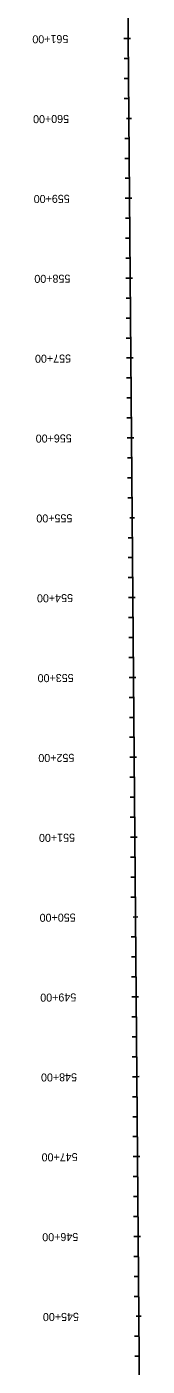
# Model space of a CAD drawing. Extents: x 23417911 to 23421158, y 6737892 to 6791804.
# Drawn here: x 23420755 to 23420891, y 6780008 to 6781685 of the extents above; entities that cross this region are included whole.
import ezdxf

# ---------------------------------------------------------------- set-up
doc = ezdxf.new("R2010")
doc.units = 0
for name, color, linetype in [('Alignment', 7, 'Continuous'), ('TextAlignmentLrg', 7, 'Continuous'), ('TextAlignmentSml', 7, 'Continuous')]:
    doc.layers.add(name, color=color, linetype=linetype)

msp = doc.modelspace()

# ---------------------------------------------------------------- linework, layer by layer
at = {"layer": 'Alignment'}
msp.add_line((23420888.7, 6779969.4), (23420840.8, 6785772.8), dxfattribs=at)
msp.add_line((23420888.7, 6779969.4), (23420840.8, 6785772.8), dxfattribs=at)
at = {"layer": 'TextAlignmentLrg'}
for p, q in [((23420874.7, 6781670.2), (23420869.2, 6781670.1)), ((23420872.4, 6781570.2), (23420878.6, 6781570.2)), ((23420876.3, 6781470.2), (23420870.9, 6781470.2)), ((23420877.2, 6781370.2), (23420871.7, 6781370.2)), ((23420878, 6781270.2), (23420872.5, 6781270.2)), ((23420878.8, 6781170.2), (23420873.3, 6781170.2)), ((23420876.6, 6781070.2), (23420882.7, 6781070.2)), ((23420880.5, 6780970.2), (23420875, 6780970.2)), ((23420881.3, 6780870.2), (23420875.8, 6780870.2)), ((23420882.1, 6780770.2), (23420876.6, 6780770.2)), ((23420882.9, 6780670.2), (23420877.5, 6780670.2)), ((23420880.7, 6780570.2), (23420886.8, 6780570.3)), ((23420884.6, 6780470.2), (23420879.1, 6780470.2)), ((23420885.4, 6780370.2), (23420879.9, 6780370.2)), ((23420886.2, 6780270.2), (23420880.8, 6780270.2)), ((23420887.1, 6780170.2), (23420881.6, 6780170.2)), ((23420884.8, 6780070.2), (23420890.9, 6780070.3))]:
    msp.add_line(p, q, dxfattribs=at)
at = {"layer": 'TextAlignmentSml'}
for p, q in [((23420871.6, 6781670.2), (23420877.7, 6781670.2)), ((23420874.9, 6781645.2), (23420869.4, 6781645.1)), ((23420875.1, 6781620.2), (23420869.6, 6781620.1)), ((23420875.3, 6781595.2), (23420869.8, 6781595.1)), ((23420872.4, 6781570.2), (23420878.6, 6781570.2)), ((23420875.7, 6781545.2), (23420870.3, 6781545.2)), ((23420875.9, 6781520.2), (23420870.5, 6781520.2)), ((23420876.1, 6781495.2), (23420870.7, 6781495.2)), ((23420873.3, 6781470.2), (23420879.4, 6781470.2)), ((23420876.5, 6781445.2), (23420871.1, 6781445.2)), ((23420876.7, 6781420.2), (23420871.3, 6781420.2)), ((23420876.9, 6781395.2), (23420871.5, 6781395.2)), ((23420874.1, 6781370.2), (23420880.2, 6781370.2)), ((23420877.4, 6781345.2), (23420871.9, 6781345.2)), ((23420877.6, 6781320.2), (23420872.1, 6781320.2)), ((23420877.8, 6781295.2), (23420872.3, 6781295.2)), ((23420874.9, 6781270.2), (23420881, 6781270.2)), ((23420878.2, 6781245.2), (23420872.7, 6781245.2)), ((23420878.4, 6781220.2), (23420872.9, 6781220.2)), ((23420878.6, 6781195.2), (23420873.1, 6781195.2)), ((23420875.7, 6781170.2), (23420881.9, 6781170.2)), ((23420879, 6781145.2), (23420873.6, 6781145.2)), ((23420879.2, 6781120.2), (23420873.8, 6781120.2)), ((23420879.4, 6781095.2), (23420874, 6781095.2)), ((23420876.6, 6781070.2), (23420882.7, 6781070.2)), ((23420879.8, 6781045.2), (23420874.4, 6781045.2)), ((23420880, 6781020.2), (23420874.6, 6781020.2)), ((23420880.2, 6780995.2), (23420874.8, 6780995.2)), ((23420877.4, 6780970.2), (23420883.5, 6780970.2)), ((23420880.7, 6780945.2), (23420875.2, 6780945.2)), ((23420880.9, 6780920.2), (23420875.4, 6780920.2)), ((23420881.1, 6780895.2), (23420875.6, 6780895.2)), ((23420878.2, 6780870.2), (23420884.3, 6780870.2)), ((23420881.5, 6780845.2), (23420876, 6780845.2)), ((23420881.7, 6780820.2), (23420876.2, 6780820.2)), ((23420881.9, 6780795.2), (23420876.4, 6780795.2)), ((23420879, 6780770.2), (23420885.2, 6780770.2)), ((23420882.3, 6780745.2), (23420876.9, 6780745.2)), ((23420882.5, 6780720.2), (23420877.1, 6780720.2)), ((23420882.7, 6780695.2), (23420877.3, 6780695.2)), ((23420879.9, 6780670.2), (23420886, 6780670.3)), ((23420883.1, 6780645.2), (23420877.7, 6780645.2)), ((23420883.3, 6780620.2), (23420877.9, 6780620.2)), ((23420883.5, 6780595.2), (23420878.1, 6780595.2)), ((23420880.7, 6780570.2), (23420886.8, 6780570.3)), ((23420884, 6780545.2), (23420878.5, 6780545.2)), ((23420884.2, 6780520.2), (23420878.7, 6780520.2)), ((23420884.4, 6780495.2), (23420878.9, 6780495.2)), ((23420881.5, 6780470.2), (23420887.6, 6780470.3)), ((23420884.8, 6780445.2), (23420879.3, 6780445.2)), ((23420885, 6780420.2), (23420879.5, 6780420.2)), ((23420885.2, 6780395.2), (23420879.7, 6780395.2)), ((23420882.3, 6780370.2), (23420888.5, 6780370.3)), ((23420885.6, 6780345.2), (23420880.2, 6780345.2)), ((23420885.8, 6780320.2), (23420880.4, 6780320.2)), ((23420886, 6780295.2), (23420880.6, 6780295.2)), ((23420883.2, 6780270.2), (23420889.3, 6780270.3)), ((23420886.4, 6780245.2), (23420881, 6780245.2)), ((23420886.6, 6780220.2), (23420881.2, 6780220.2)), ((23420886.8, 6780195.2), (23420881.4, 6780195.2)), ((23420884, 6780170.2), (23420890.1, 6780170.3)), ((23420887.3, 6780145.2), (23420881.8, 6780145.2)), ((23420887.5, 6780120.2), (23420882, 6780120.2)), ((23420887.7, 6780095.2), (23420882.2, 6780095.2)), ((23420884.8, 6780070.2), (23420890.9, 6780070.3)), ((23420888.1, 6780045.2), (23420882.6, 6780045.2)), ((23420888.3, 6780020.2), (23420882.8, 6780020.2))]:
    msp.add_line(p, q, dxfattribs=at)

# ---------------------------------------------------------------- texts
at = {"layer": 'TextAlignmentLrg'}
for s, p in [('560+00', (23420800.5, 6781574.6)), ('555+00', (23420804.6, 6781074.6)), ('550+00', (23420808.7, 6780574.6)), ('545+00', (23420812.8, 6780074.6))]:
    msp.add_text(s, height=10.02, rotation=180.4726, dxfattribs=at).set_placement(p)
at = {"layer": 'TextAlignmentSml'}
for s, p in [('561+00', (23420799.6, 6781674.6)), ('560+00', (23420800.5, 6781574.6)), ('559+00', (23420801.3, 6781474.6)), ('558+00', (23420802.1, 6781374.6)), ('557+00', (23420802.9, 6781274.6)), ('556+00', (23420803.8, 6781174.6)), ('555+00', (23420804.6, 6781074.6)), ('554+00', (23420805.4, 6780974.6)), ('553+00', (23420806.2, 6780874.6)), ('552+00', (23420807.1, 6780774.6)), ('551+00', (23420807.9, 6780674.6)), ('550+00', (23420808.7, 6780574.6)), ('549+00', (23420809.5, 6780474.6)), ('548+00', (23420810.4, 6780374.6)), ('547+00', (23420811.2, 6780274.6)), ('546+00', (23420812, 6780174.6)), ('545+00', (23420812.8, 6780074.6))]:
    msp.add_text(s, height=10.02, rotation=180.4726, dxfattribs=at).set_placement(p)

doc.saveas('drawing.dxf')
